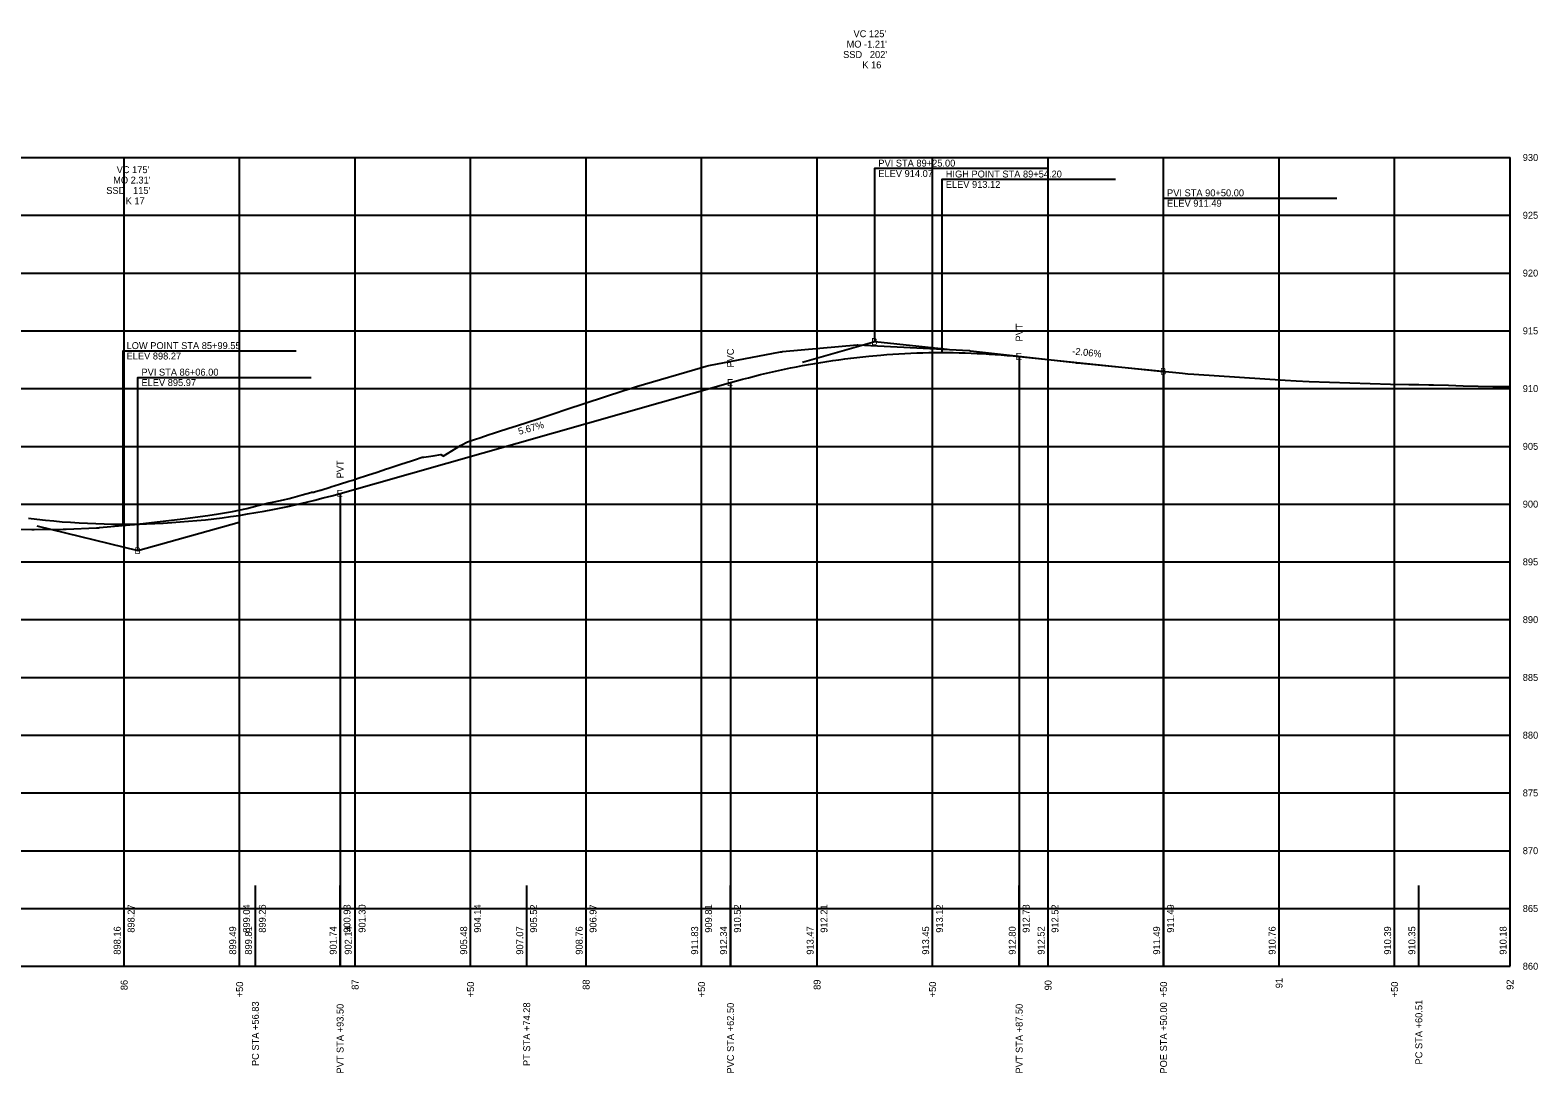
# Model space of a CAD drawing. Extents: x 76292 to 78417, y 50412 to 52585.
# Drawn here: x 76965 to 77617, y 52134 to 52585 of the extents above; entities that cross this region are included whole.
import ezdxf

# ---------------------------------------------------------------- set-up
doc = ezdxf.new("R2010")
doc.units = 0
for name, color, linetype in [('1', 7, 'Continuous'), ('2', 7, 'Continuous'), ('3', 7, 'Continuous'), ('32', 7, 'Continuous'), ('33', 7, 'Continuous'), ('63', 7, 'Continuous')]:
    doc.layers.add(name, color=color, linetype=linetype)

msp = doc.modelspace()

# ---------------------------------------------------------------- linework, layer by layer
at = {"layer": '1'}
for p, q in [((76305.34, 52180.05), (77605.34, 52180.05)), ((77005.34, 52180.05), (77005.34, 52180.05)), ((77055.34, 52180.05), (77055.34, 52180.05)), ((77105.34, 52180.05), (77105.34, 52180.05)), ((77155.34, 52180.05), (77155.34, 52180.05)), ((77205.34, 52180.05), (77205.34, 52180.05)), ((77255.34, 52180.05), (77255.34, 52180.05)), ((77305.34, 52180.05), (77305.34, 52180.05)), ((77355.34, 52180.05), (77355.34, 52180.05)), ((77405.34, 52180.05), (77405.34, 52180.05)), ((77455.34, 52180.05), (77455.34, 52180.05)), ((77505.34, 52180.05), (77505.34, 52180.05)), ((77555.34, 52180.05), (77555.34, 52180.05)), ((77605.34, 52180.05), (77605.34, 52180.05))]:
    msp.add_line(p, q, dxfattribs=at)
for points in [[(77330.34, 52450.37), (77330.34, 52525.37), (77405.34, 52525.37)], [(77359.54, 52445.65), (77359.54, 52520.65), (77434.54, 52520.65)], [(77455.34, 52437.5), (77455.34, 52512.5), (77530.34, 52512.5)], [(77004.89, 52371.39), (77004.89, 52446.39), (77079.89, 52446.39)], [(77392.84, 52443.93), (77392.84, 52180.05), (77392.84, 52180.05), (77392.84, 52180.05)], [(77011.34, 52359.9), (77011.34, 52434.9), (77086.34, 52434.9)], [(77455.34, 52437.5), (77455.34, 52180.05), (77455.34, 52180.05), (77455.34, 52180.05)], [(77267.84, 52432.64), (77267.84, 52180.05), (77267.84, 52180.05), (77267.84, 52180.05)], [(77098.84, 52384.71), (77098.84, 52180.05), (77098.84, 52180.05), (77098.84, 52180.05)], [(77005.34, 52180.05), (77005.34, 52215.05)], [(77005.34, 52180.05), (77005.34, 52215.05)], [(77005.34, 52180.05), (77005.34, 52215.05)], [(77005.34, 52180.05), (77005.34, 52215.05)], [(77055.34, 52180.05), (77055.34, 52215.05)], [(77055.34, 52180.05), (77055.34, 52215.05)], [(77055.34, 52180.05), (77055.34, 52215.05)], [(77055.34, 52180.05), (77055.34, 52215.05)], [(77062.17, 52180.05), (77062.17, 52215.05)], [(77062.17, 52180.05), (77062.17, 52215.05)], [(77062.17, 52180.05), (77062.17, 52215.05)], [(77062.17, 52180.05), (77062.17, 52215.05)], [(77098.84, 52180.05), (77098.84, 52215.05)], [(77098.84, 52180.05), (77098.84, 52215.05)], [(77098.84, 52180.05), (77098.84, 52215.05)], [(77098.84, 52180.05), (77098.84, 52215.05)], [(77105.34, 52180.05), (77105.34, 52215.05)], [(77105.34, 52180.05), (77105.34, 52215.05)], [(77105.34, 52180.05), (77105.34, 52215.05)], [(77105.34, 52180.05), (77105.34, 52215.05)], [(77155.34, 52180.05), (77155.34, 52215.05)], [(77155.34, 52180.05), (77155.34, 52215.05)], [(77155.34, 52180.05), (77155.34, 52215.05)], [(77155.34, 52180.05), (77155.34, 52215.05)], [(77179.62, 52180.05), (77179.62, 52215.05)], [(77179.62, 52180.05), (77179.62, 52215.05)], [(77179.62, 52180.05), (77179.62, 52215.05)], [(77179.62, 52180.05), (77179.62, 52215.05)], [(77205.34, 52180.05), (77205.34, 52215.05)], [(77205.34, 52180.05), (77205.34, 52215.05)], [(77205.34, 52180.05), (77205.34, 52215.05)], [(77205.34, 52180.05), (77205.34, 52215.05)], [(77255.34, 52180.05), (77255.34, 52215.05)], [(77255.34, 52180.05), (77255.34, 52215.05)], [(77255.34, 52180.05), (77255.34, 52215.05)], [(77255.34, 52180.05), (77255.34, 52215.05)], [(77267.84, 52180.05), (77267.84, 52215.05)], [(77267.84, 52180.05), (77267.84, 52215.05)], [(77267.84, 52180.05), (77267.84, 52215.05)], [(77267.84, 52180.05), (77267.84, 52215.05)], [(77305.34, 52180.05), (77305.34, 52215.05)], [(77305.34, 52180.05), (77305.34, 52215.05)], [(77305.34, 52180.05), (77305.34, 52215.05)], [(77305.34, 52180.05), (77305.34, 52215.05)], [(77355.34, 52180.05), (77355.34, 52215.05)], [(77355.34, 52180.05), (77355.34, 52215.05)], [(77355.34, 52180.05), (77355.34, 52215.05)], [(77355.34, 52180.05), (77355.34, 52215.05)], [(77392.84, 52180.05), (77392.84, 52215.05)], [(77392.84, 52180.05), (77392.84, 52215.05)], [(77392.84, 52180.05), (77392.84, 52215.05)], [(77392.84, 52180.05), (77392.84, 52215.05)], [(77405.34, 52180.05), (77405.34, 52215.05)], [(77405.34, 52180.05), (77405.34, 52215.05)], [(77405.34, 52180.05), (77405.34, 52215.05)], [(77405.34, 52180.05), (77405.34, 52215.05)], [(77455.34, 52180.05), (77455.34, 52215.05)], [(77455.34, 52180.05), (77455.34, 52215.05)], [(77455.34, 52180.05), (77455.34, 52215.05)], [(77455.34, 52180.05), (77455.34, 52215.05)], [(77505.34, 52180.05), (77505.34, 52215.05)], [(77505.34, 52180.05), (77505.34, 52215.05)], [(77505.34, 52180.05), (77505.34, 52215.05)], [(77505.34, 52180.05), (77505.34, 52215.05)], [(77555.34, 52180.05), (77555.34, 52215.05)], [(77555.34, 52180.05), (77555.34, 52215.05)], [(77555.34, 52180.05), (77555.34, 52215.05)], [(77555.34, 52180.05), (77555.34, 52215.05)], [(77565.85, 52180.05), (77565.85, 52215.05)], [(77565.85, 52180.05), (77565.85, 52215.05)], [(77565.85, 52180.05), (77565.85, 52215.05)], [(77565.85, 52180.05), (77565.85, 52215.05)], [(77605.34, 52180.05), (77605.34, 52215.05)], [(77605.34, 52180.05), (77605.34, 52215.05)], [(77605.34, 52180.05), (77605.34, 52215.05)], [(77605.34, 52180.05), (77605.34, 52215.05)]]:
    msp.add_lwpolyline(points, dxfattribs=at)
at = {"layer": '2'}
msp.add_lwpolyline([(76949.25, 52369.31), (76965.37, 52369.09), (76966.35, 52369.11), (76978.99, 52369.17), (76980.24, 52369.21), (76993.41, 52369.79), (76994.2, 52369.82), (76994.68, 52369.86), (77007.77, 52371.09), (77011.88, 52371.43), (77012.32, 52371.5), (77029.54, 52373.47), (77041.52, 52375.07), (77046.22, 52375.8), (77052.31, 52376.86), (77058.4, 52378.15), (77062.17, 52379.1), (77066.22, 52380.14), (77067.32, 52380.42), (77070.27, 52381.05), (77074.32, 52381.92), (77076.77, 52382.45), (77078.37, 52382.9), (77082.42, 52384.05), (77086.23, 52385.13), (77086.47, 52385.16), (77087.51, 52385.28), (77087.81, 52385.35), (77090.27, 52386.06), (77090.52, 52386.14), (77094.57, 52387.4), (77094.87, 52387.5), (77098.62, 52388.66), (77102.67, 52389.93), (77104.38, 52390.46), (77106.72, 52391.21), (77110.32, 52392.38), (77110.77, 52392.53), (77114.82, 52393.89), (77118.87, 52395.26), (77119.54, 52395.49), (77122.92, 52396.59), (77125.57, 52397.46), (77126.97, 52397.91), (77130.22, 52398.96), (77131.02, 52399.22), (77134.4, 52400.3), (77135.07, 52400.4), (77139.12, 52401.01), (77142.46, 52401.51), (77143.17, 52401.06), (77143.48, 52400.86), (77147.22, 52403.13), (77151.03, 52405.46), (77151.27, 52405.58), (77153.95, 52407.02), (77155.32, 52407.46), (77157.5, 52408.17), (77159.37, 52408.78), (77163.42, 52410.11), (77165.27, 52410.72), (77167.47, 52411.43), (77171.52, 52412.74), (77175.57, 52414.05), (77179.62, 52415.37), (77185.09, 52417.16), (77191.52, 52419.32), (77196.63, 52421.01), (77221.68, 52429.19), (77224.61, 52430.14), (77227.2, 52430.93), (77255.91, 52439.36), (77257.25, 52439.71), (77258.5, 52439.97), (77289.45, 52445.89), (77289.96, 52445.98), (77290.43, 52446.05), (77322.75, 52448.92), (77322.82, 52448.93), (77322.87, 52448.93), (77322.91, 52448.92), (77371.17, 52446.48), (77371.31, 52446.47), (77371.45, 52446.46), (77371.58, 52446.45), (77371.71, 52446.43), (77417.11, 52441.32), (77417.37, 52441.29), (77417.64, 52441.26), (77418.23, 52441.19), (77463.52, 52436.7), (77465.86, 52436.46), (77468.4, 52436.24), (77508.05, 52433.66), (77512.78, 52433.35), (77518.31, 52433.15), (77553.52, 52432.01), (77561.48, 52431.85), (77565.85, 52431.79), (77570.14, 52431.74), (77572.26, 52431.67), (77578.66, 52431.47), (77585.07, 52431.28), (77591.48, 52431.09), (77597.88, 52430.91), (77598.48, 52430.9), (77604.29, 52430.93), (77605.34, 52430.94)], dxfattribs=at)
at = {"layer": '32'}
for p, q in [((77392.84, 52443.93), (77455.34, 52437.5)), ((77098.84, 52384.71), (77267.84, 52432.64))]:
    msp.add_line(p, q, dxfattribs=at)
for points in [[(77299.09, 52441.51), (77330.34, 52450.37), (77361.59, 52447.15)], [(77267.84, 52432.64), (77270.44, 52433.37), (77273.05, 52434.08), (77275.65, 52434.77), (77278.26, 52435.43), (77280.86, 52436.08), (77283.46, 52436.7), (77286.07, 52437.3), (77288.67, 52437.88), (77291.28, 52438.44), (77293.88, 52438.98), (77296.49, 52439.5), (77299.09, 52440), (77301.69, 52440.47), (77304.3, 52440.93), (77306.9, 52441.36), (77309.51, 52441.78), (77312.11, 52442.17), (77314.71, 52442.54), (77317.32, 52442.89), (77319.92, 52443.22), (77322.53, 52443.53), (77325.13, 52443.82), (77327.74, 52444.08), (77332.94, 52444.55), (77335.55, 52444.76), (77338.15, 52444.94), (77340.76, 52445.1), (77343.36, 52445.24), (77345.96, 52445.36), (77348.57, 52445.46), (77351.17, 52445.54), (77353.78, 52445.6), (77356.38, 52445.63), (77358.99, 52445.65), (77361.59, 52445.64), (77364.19, 52445.61), (77366.8, 52445.57), (77369.4, 52445.5), (77372.01, 52445.41), (77374.61, 52445.3), (77377.21, 52445.17), (77379.82, 52445.01), (77382.42, 52444.84), (77385.03, 52444.64), (77387.63, 52444.43), (77390.24, 52444.19), (77392.84, 52443.93)], [(76963.94, 52373.92), (76967.59, 52373.49), (76971.24, 52373.1), (76974.88, 52372.75), (76978.53, 52372.44), (76982.17, 52372.17), (76985.82, 52371.94), (76989.46, 52371.75), (76993.11, 52371.6), (76996.76, 52371.49), (77000.4, 52371.42), (77004.05, 52371.39), (77007.69, 52371.4), (77014.99, 52371.54), (77018.63, 52371.67), (77022.28, 52371.85), (77025.92, 52372.06), (77029.57, 52372.31), (77033.21, 52372.6), (77036.86, 52372.93), (77040.51, 52373.3), (77044.15, 52373.72), (77047.8, 52374.17), (77051.44, 52374.66), (77055.09, 52375.19), (77058.74, 52375.77), (77062.38, 52376.38), (77066.03, 52377.03), (77069.67, 52377.72), (77073.32, 52378.46), (77076.96, 52379.23), (77080.61, 52380.04), (77084.26, 52380.9), (77087.9, 52381.79), (77091.55, 52382.72), (77095.19, 52383.7), (77098.84, 52384.71)], [(76967.59, 52370.6), (77011.34, 52359.9), (77055.09, 52372.3)]]:
    msp.add_lwpolyline(points, dxfattribs=at)
at = {"layer": '63'}
for p, q in [((76305.34, 52530.05), (77605.34, 52530.05)), ((76305.34, 52530.05), (77605.34, 52530.05)), ((77005.34, 52180.05), (77005.34, 52530.05)), ((77055.34, 52180.05), (77055.34, 52530.05)), ((77105.34, 52180.05), (77105.34, 52530.05)), ((77155.34, 52180.05), (77155.34, 52530.05)), ((77205.34, 52180.05), (77205.34, 52530.05)), ((77255.34, 52180.05), (77255.34, 52530.05)), ((77305.34, 52180.05), (77305.34, 52530.05)), ((77355.34, 52180.05), (77355.34, 52530.05)), ((77405.34, 52180.05), (77405.34, 52530.05)), ((77455.34, 52180.05), (77455.34, 52530.05)), ((77505.34, 52180.05), (77505.34, 52530.05)), ((77555.34, 52180.05), (77555.34, 52530.05)), ((77605.34, 52180.05), (77605.34, 52530.05)), ((77605.34, 52530.05), (77605.34, 52530.05)), ((77605.34, 52530.05), (77605.34, 52530.05)), ((76305.34, 52505.05), (77605.34, 52505.05)), ((77605.34, 52505.05), (77605.34, 52505.05)), ((76305.34, 52480.05), (77605.34, 52480.05)), ((77605.34, 52480.05), (77605.34, 52480.05)), ((76305.34, 52455.05), (77605.34, 52455.05)), ((77605.34, 52455.05), (77605.34, 52455.05)), ((76305.34, 52430.05), (77605.34, 52430.05)), ((77605.34, 52430.05), (77605.34, 52430.05)), ((76305.34, 52405.05), (77605.34, 52405.05)), ((77605.34, 52405.05), (77605.34, 52405.05)), ((76305.34, 52380.05), (77605.34, 52380.05)), ((77605.34, 52380.05), (77605.34, 52380.05)), ((76305.34, 52355.05), (77605.34, 52355.05)), ((77605.34, 52355.05), (77605.34, 52355.05)), ((76305.34, 52330.05), (77605.34, 52330.05)), ((77605.34, 52330.05), (77605.34, 52330.05)), ((76305.34, 52305.05), (77605.34, 52305.05)), ((77605.34, 52305.05), (77605.34, 52305.05)), ((76305.34, 52280.05), (77605.34, 52280.05)), ((77605.34, 52280.05), (77605.34, 52280.05)), ((76305.34, 52255.05), (77605.34, 52255.05)), ((77605.34, 52255.05), (77605.34, 52255.05)), ((76305.34, 52230.05), (77605.34, 52230.05)), ((77605.34, 52230.05), (77605.34, 52230.05)), ((76305.34, 52205.05), (77605.34, 52205.05)), ((77605.34, 52205.05), (77605.34, 52205.05)), ((77605.34, 52180.05), (77605.34, 52180.05))]:
    msp.add_line(p, q, dxfattribs=at)

# ---------------------------------------------------------------- texts
at = {"layer": '1'}
for s, p in [('86', (77006.84, 52169.68)), ('+50', (77056.84, 52166.59)), ('87', (77106.84, 52169.85)), ('+50', (77156.84, 52166.59)), ('88', (77206.84, 52169.85)), ('+50', (77256.84, 52166.59)), ('89', (77306.84, 52169.82)), ('+50', (77356.84, 52166.59)), ('90', (77406.84, 52169.59)), ('+50', (77456.84, 52166.59)), ('91', (77506.84, 52170.53)), ('+50', (77556.84, 52166.59)), ('92', (77606.84, 52169.85))]:
    msp.add_text(s, height=3, rotation=90, dxfattribs=at).set_placement(p)
at = {"layer": '3'}
for s, p in [('898.16', (77003.84, 52185.05)), ('899.49', (77053.84, 52185.05)), ('899.81', (77060.67, 52185.05)), ('901.74', (77097.34, 52185.05)), ('902.14', (77103.84, 52185.05)), ('905.48', (77153.84, 52185.05)), ('907.07', (77178.12, 52185.05)), ('908.76', (77203.84, 52185.05)), ('911.83', (77253.84, 52185.05)), ('912.34', (77266.34, 52185.05)), ('913.47', (77303.84, 52185.05)), ('913.45', (77353.84, 52185.05)), ('912.80', (77391.34, 52185.05)), ('912.52', (77403.84, 52185.05)), ('911.49', (77453.84, 52185.05)), ('910.76', (77503.84, 52185.05)), ('910.39', (77553.84, 52185.05)), ('910.35', (77564.35, 52185.05)), ('910.18', (77603.84, 52185.05))]:
    msp.add_text(s, height=3, rotation=90, dxfattribs=at).set_placement(p)
at = {"layer": '33'}
for s, p in [("VC 125'", (77321.1, 52582.12)), ("MO -1.21'", (77318.1, 52577.62)), ("SSD   202'", (77316.6, 52573.12)), ('K 16', (77324.91, 52568.62)), ("VC 175'", (77002.1, 52523.29)), ("MO 2.31'", (77000.6, 52518.79)), ("SSD   115'", (76997.6, 52514.29)), ('K 17', (77005.99, 52509.79)), ('B', (77328.84, 52448.87)), ('B', (77453.84, 52436)), ('B', (77009.84, 52358.4))]:
    msp.add_text(s, height=3, dxfattribs=at).set_placement(p)
for s, rotation, p in [('PVI STA 89+25.00', 360, (77331.84, 52526.12)), ('ELEV 914.07', 360, (77331.84, 52521.62)), ('HIGH POINT STA 89+54.20', 360, (77361.04, 52521.4)), ('ELEV 913.12', 360, (77361.04, 52516.9)), ('PVI STA 90+50.00', 360, (77456.84, 52513.25)), ('ELEV 911.49', 360, (77456.84, 52508.75)), ('PVT', 90, (77394.34, 52450.43)), ('LOW POINT STA 85+99.55', 360, (77006.39, 52447.14)), ('PVC', 90, (77269.34, 52439.14)), ('-2.06%', 354.11927, (77415.71, 52444.83)), ('ELEV 898.27', 360, (77006.39, 52442.64)), ('E', 360, (77391.34, 52442.43)), ('PVI STA 86+06.00', 360, (77012.84, 52435.65)), ('ELEV 895.97', 360, (77012.84, 52431.15)), ('E', 360, (77266.34, 52431.14)), ('5.67%', 15.83443, (77176.4, 52409.99)), ('PVT', 90, (77100.34, 52391.21)), ('E', 360, (77097.34, 52383.21)), ('898.27', 90, (77009.84, 52194.55)), ('899.04', 90, (77059.84, 52194.55)), ('899.26', 90, (77066.67, 52194.55)), ('900.93', 90, (77103.34, 52194.55)), ('901.30', 90, (77109.84, 52194.55)), ('904.14', 90, (77159.84, 52194.55)), ('905.52', 90, (77184.12, 52194.55)), ('906.97', 90, (77209.84, 52194.55)), ('909.81', 90, (77259.84, 52194.55)), ('910.52', 90, (77272.34, 52194.55)), ('912.21', 90, (77309.84, 52194.55)), ('913.12', 90, (77359.84, 52194.55)), ('912.78', 90, (77397.34, 52194.55)), ('912.52', 90, (77409.84, 52194.55)), ('911.49', 90, (77459.84, 52194.55)), ('PC STA +56.83', 90, (77063.67, 52136.85)), ('PVT STA +93.50', 90, (77100.34, 52133.59)), ('PT STA +74.28', 90, (77181.12, 52136.85)), ('PVC STA +62.50', 90, (77269.34, 52133.59)), ('PVT STA +87.50', 90, (77394.34, 52133.59)), ('POE STA +50.00', 90, (77456.84, 52133.59)), ('PC STA +60.51', 90, (77567.35, 52137.53))]:
    msp.add_text(s, height=3, rotation=rotation, dxfattribs=at).set_placement(p)
at = {"layer": '63'}
for s, p in [('930', (77610.84, 52528.55)), ('930', (77610.84, 52528.55)), ('925', (77610.84, 52503.55)), ('920', (77610.84, 52478.55)), ('915', (77610.84, 52453.55)), ('910', (77610.84, 52428.55)), ('905', (77610.84, 52403.55)), ('900', (77610.84, 52378.55)), ('895', (77610.84, 52353.55)), ('890', (77610.84, 52328.55)), ('885', (77610.84, 52303.55)), ('880', (77610.84, 52278.55)), ('875', (77610.84, 52253.55)), ('870', (77610.84, 52228.55)), ('865', (77610.84, 52203.55)), ('860', (77610.84, 52178.55))]:
    msp.add_text(s, height=3, dxfattribs=at).set_placement(p)

doc.saveas('drawing.dxf')
